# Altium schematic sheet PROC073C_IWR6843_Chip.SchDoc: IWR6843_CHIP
size 431 x 279 mm; Date: Not shown in title block; ApprovedBy: Not shown in title block; CheckedBy: Not shown in title block; Author: Not shown in title block; CompanyName: Not shown in title block; DrawnBy: Charles F. Oladimeji; Engineer: Not shown in title block; Organization: Not shown in title block; Address1: Not shown in title block; Address2: Not shown in title block; Address3: Not shown in title block; Address4: Not shown in title block; DocumentNumber: 4; Revision: Use project parameter SCH_Rev; SheetNumber: 4; SheetTotal: 13; PageSetup: Record=PageOptions¦CenterHorizontal=True¦CenterVertical=True¦PrintScale=1.00¦XCorrection=1.00¦YCorrection=1.00¦PrintKind=0¦BorderSize=5000000¦LeftOffset=0¦BottomOffset=0¦Orientation=2¦PaperLength=1000¦PaperWidth=1000¦Scale=100¦PaperSource=15¦PrintQuality=600¦MediaType=1¦DitherType=10¦PaperKind=Letter¦PrintScaleMode=1
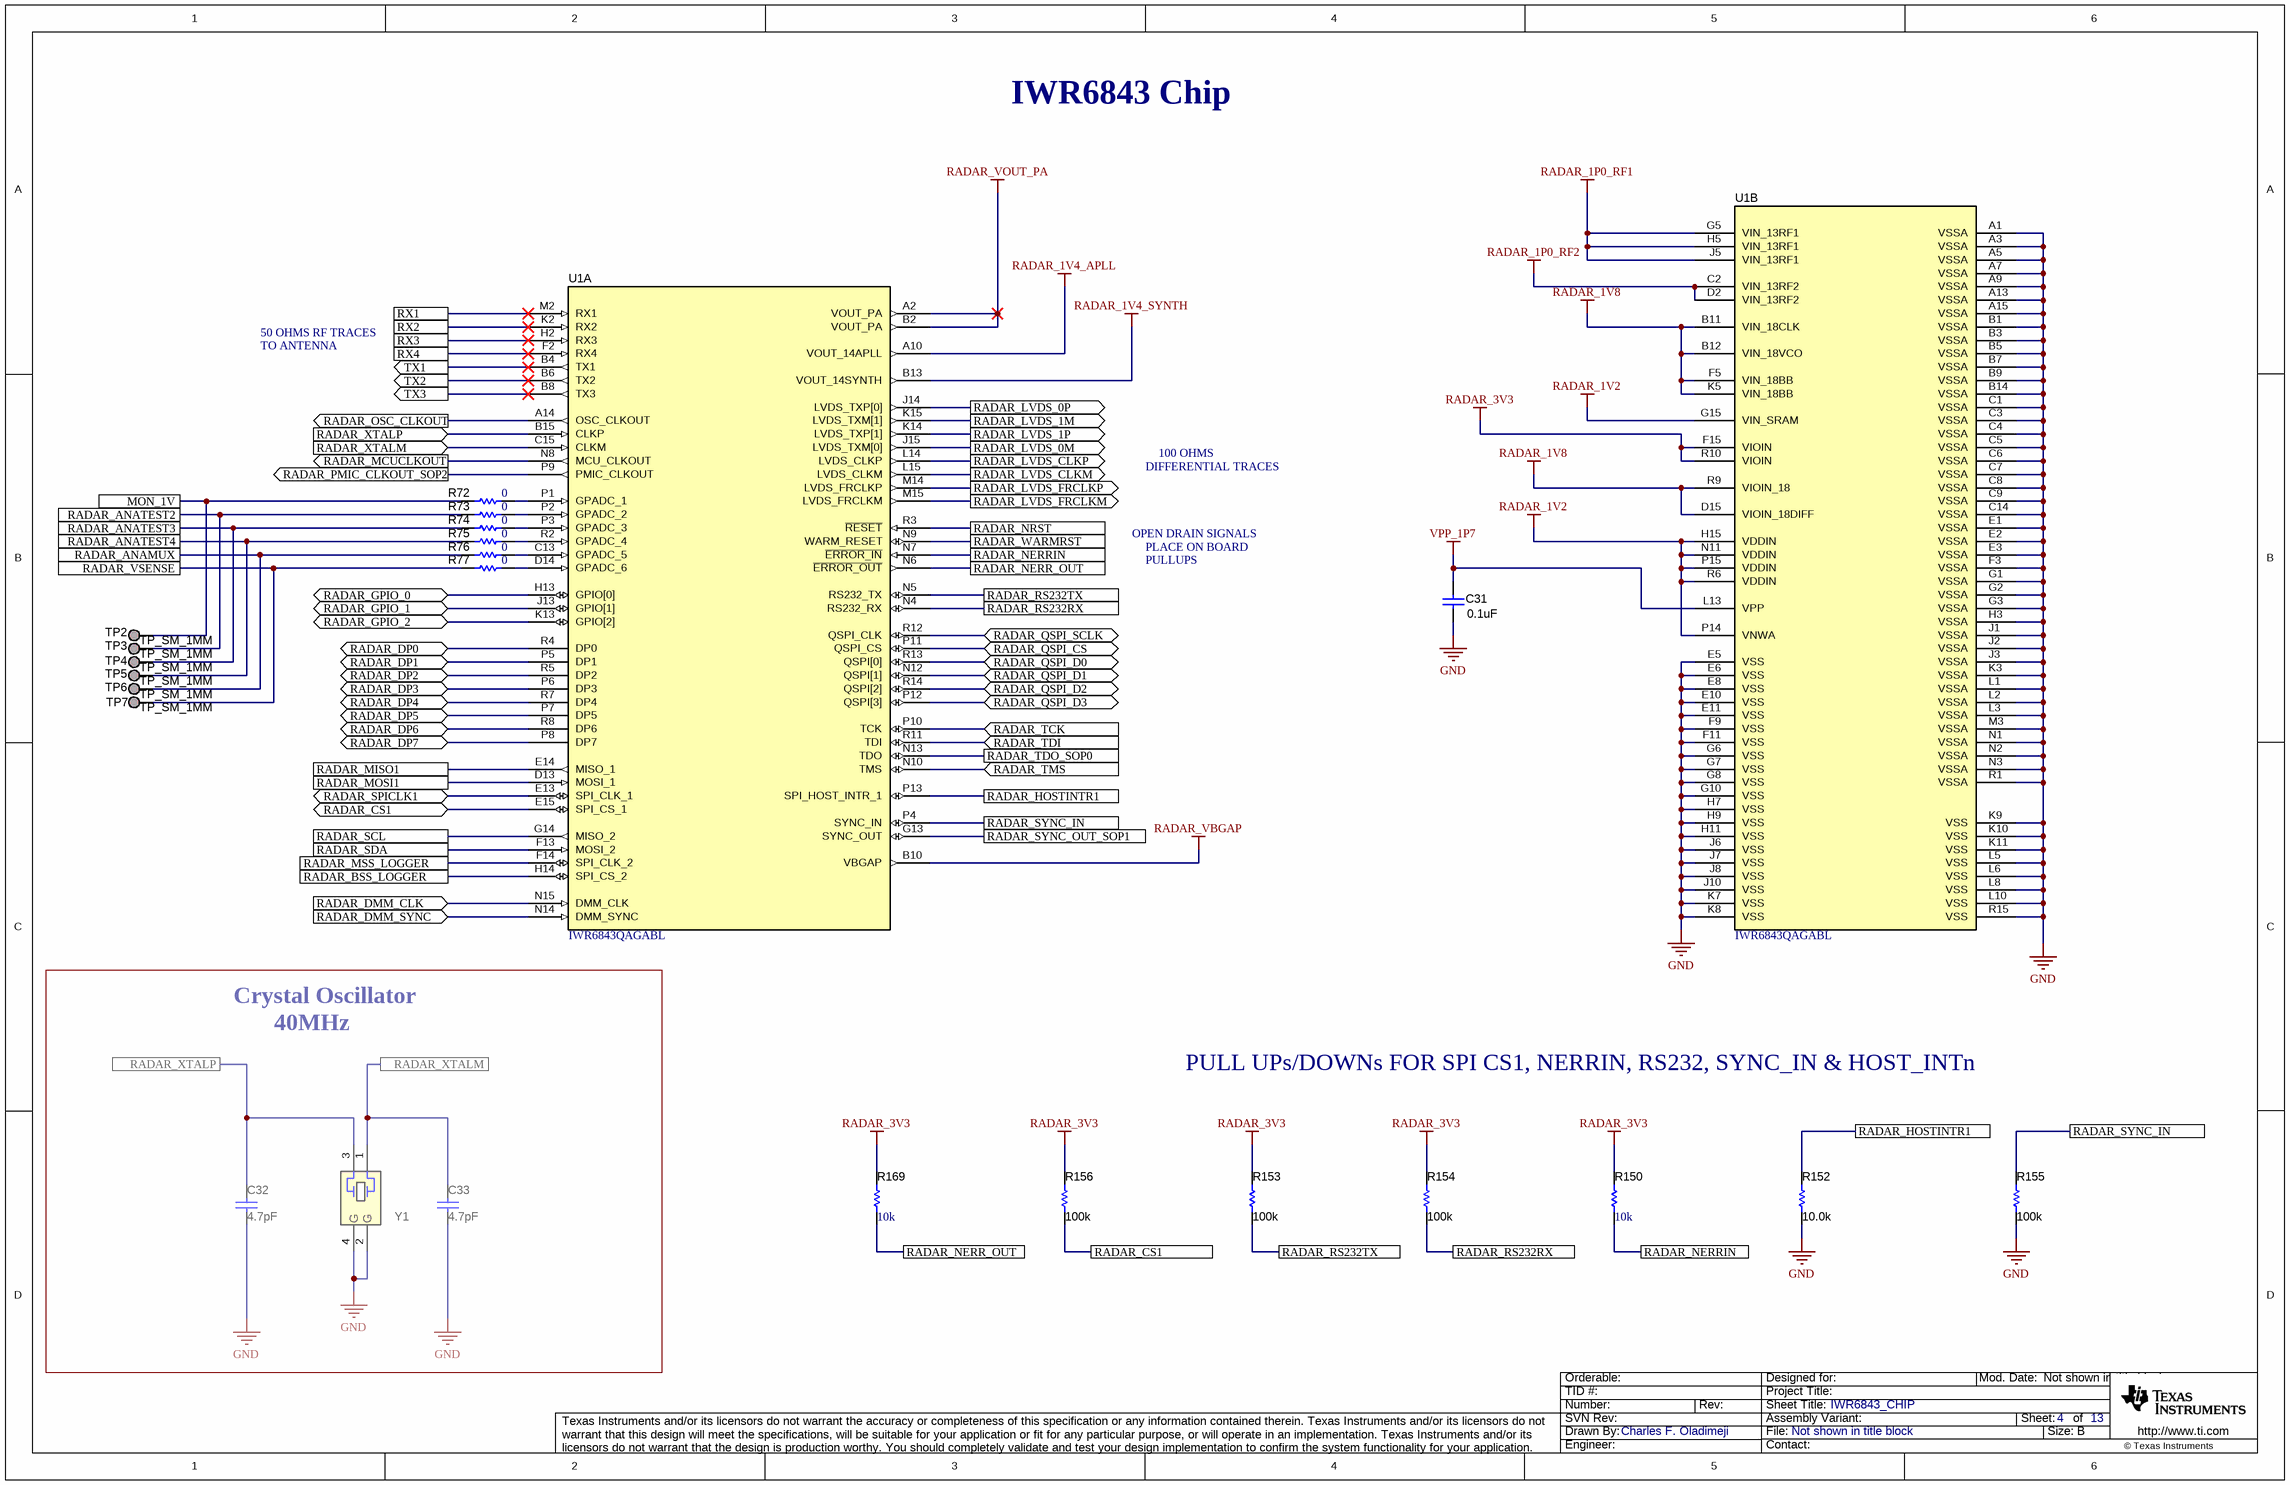
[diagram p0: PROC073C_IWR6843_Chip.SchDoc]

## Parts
C31  ValueDisplayed: 0.1uF  [0201]  (hidden comment: GRM033C71A104KE14D)
C32  ValueDisplayed: 4.7pF  [0402L]  (hidden comment: GJM1555C1H4R7BB01D)
C33  ValueDisplayed: 4.7pF  [0402L]  (hidden comment: GJM1555C1H4R7BB01D)
R72  ValueDisplayed: 0  [0402]  (hidden comment: ERJ-2GE0R00X)
R73  ValueDisplayed: 0  [0402]  (hidden comment: ERJ-2GE0R00X)
R74  ValueDisplayed: 0  [0402]  (hidden comment: ERJ-2GE0R00X)
R75  ValueDisplayed: 0  [0402]  (hidden comment: ERJ-2GE0R00X)
R76  ValueDisplayed: 0  [0402]  (hidden comment: ERJ-2GE0R00X)
R77  ValueDisplayed: 0  [0402]  (hidden comment: ERJ-2GE0R00X)
R150  value 10k  [0402]  (hidden comment: CRCW040210K0JNED)
R152  ValueDisplayed: 10.0k  [0402L]  (hidden comment: CRCW040210K0FKED)
R153  ValueDisplayed: 100k  [0402L]  (hidden comment: CRCW0402100KFKED)
R154  ValueDisplayed: 100k  [0402L]  (hidden comment: CRCW0402100KFKED)
R155  ValueDisplayed: 100k  [0402L]  (hidden comment: CRCW0402100KFKED)
R156  ValueDisplayed: 100k  [0402L]  (hidden comment: CRCW0402100KFKED)
R169  value 10k  [0402]  (hidden comment: CRCW040210K0JNED)
TP2  TP_SM_1MM  [TP_SM_1MM]  (no BOM)
TP3  TP_SM_1MM  [TP_SM_1MM]  (no BOM)
TP4  TP_SM_1MM  [TP_SM_1MM]  (no BOM)
TP5  TP_SM_1MM  [TP_SM_1MM]  (no BOM)
TP6  TP_SM_1MM  [TP_SM_1MM]  (no BOM)
TP7  TP_SM_1MM  [TP_SM_1MM]  (no BOM)
U1  IWR6843QAGABL  [ABL0161B]  (parts A,B of 2)
Y1  CX3225SA40000D0PTWCC  [Kyocera_CX3225SA]  (value not drawn)

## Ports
MON_1V, RADAR_ANAMUX, RADAR_ANATEST2, RADAR_ANATEST3, RADAR_ANATEST4, RADAR_BSS_LOGGER, RADAR_CS1, RADAR_CS1 (bidir), RADAR_DMM_CLK (in), RADAR_DMM_SYNC (in), RADAR_DP0 (bidir), RADAR_DP1 (bidir), RADAR_DP2 (bidir), RADAR_DP3 (bidir), RADAR_DP4 (bidir), RADAR_DP5 (bidir), RADAR_DP6 (bidir), RADAR_DP7 (bidir), RADAR_GPIO_0 (bidir), RADAR_GPIO_1 (bidir), RADAR_GPIO_2 (bidir), RADAR_HOSTINTR1, RADAR_LVDS_0M (out), RADAR_LVDS_0P (out), RADAR_LVDS_1M (out), RADAR_LVDS_1P (out), RADAR_LVDS_CLKM (out), RADAR_LVDS_CLKP (out), RADAR_LVDS_FRCLKM (out), RADAR_LVDS_FRCLKP (out), RADAR_MCUCLKOUT (out), RADAR_MISO1, RADAR_MOSI1, RADAR_MSS_LOGGER, RADAR_NERR_OUT, RADAR_NERRIN, RADAR_NRST, RADAR_OSC_CLKOUT (out), RADAR_PMIC_CLKOUT_SOP2 (out), RADAR_QSPI_CS (bidir), RADAR_QSPI_D0 (bidir), RADAR_QSPI_D1 (bidir), RADAR_QSPI_D2 (bidir), RADAR_QSPI_D3 (bidir), RADAR_QSPI_SCLK (bidir), RADAR_RS232RX, RADAR_RS232TX, RADAR_SCL, RADAR_SDA, RADAR_SPICLK1 (bidir), RADAR_SYNC_IN, RADAR_SYNC_OUT_SOP1, RADAR_TCK (in), RADAR_TDI (in), RADAR_TDO_SOP0, RADAR_TMS (in), RADAR_VSENSE, RADAR_WARMRST, RADAR_XTALM, RADAR_XTALM (in), RADAR_XTALP, RADAR_XTALP (in), RX1, RX2, RX3, RX4, TX1 (out), TX2 (out), TX3 (out)

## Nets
GND: C31.1 C32.1 C33.1 R152.1 R155.1 U1.A1(VSSA) U1.A3(VSSA) U1.A5(VSSA) U1.A7(VSSA) U1.A9(VSSA) U1.A13(VSSA) U1.A15(VSSA) U1.B1(VSSA) U1.B3(VSSA) U1.B5(VSSA) U1.B7(VSSA) U1.B9(VSSA) U1.B14(VSSA) U1.C1(VSSA) U1.C3(VSSA) U1.C4(VSSA) U1.C5(VSSA) U1.C6(VSSA) U1.C7(VSSA) U1.C8(VSSA) U1.C9(VSSA) U1.C14(VSSA) U1.E1(VSSA) U1.E2(VSSA) U1.E3(VSSA) U1.E5(VSS) U1.E6(VSS) U1.E8(VSS) U1.E10(VSS) U1.E11(VSS) U1.F3(VSSA) U1.F9(VSS) U1.F11(VSS) U1.G1(VSSA) U1.G2(VSSA) U1.G3(VSSA) U1.G6(VSS) U1.G7(VSS) U1.G8(VSS) U1.G10(VSS) U1.H3(VSSA) U1.H7(VSS) U1.H9(VSS) U1.H11(VSS) U1.J1(VSSA) U1.J2(VSSA) U1.J3(VSSA) U1.J6(VSS) U1.J7(VSS) U1.J8(VSS) U1.J10(VSS) U1.K3(VSSA) U1.K7(VSS) U1.K8(VSS) U1.K9(VSS) U1.K10(VSS) U1.K11(VSS) U1.L1(VSSA) U1.L2(VSSA) U1.L3(VSSA) U1.L5(VSS) U1.L6(VSS) U1.L8(VSS) U1.L10(VSS) U1.M3(VSSA) U1.N1(VSSA) U1.N2(VSSA) U1.N3(VSSA) U1.R1(VSSA) U1.R15(VSS) Y1.2(GND) Y1.4(GND)
RADAR_1P0_RF1: U1.G5(VIN_13RF1) U1.H5(VIN_13RF1) U1.J5(VIN_13RF1)
RADAR_1P0_RF2: U1.C2(VIN_13RF2) U1.D2(VIN_13RF2)
RADAR_1V2: U1.G15(VIN_SRAM) U1.H15(VDDIN) U1.N11(VDDIN) U1.P14(VNWA) U1.P15(VDDIN) U1.R6(VDDIN)
RADAR_1V4_APLL: U1.A10(VOUT_14APLL)
RADAR_1V4_SYNTH: U1.B13(VOUT_14SYNTH)
RADAR_1V8: U1.B11(VIN_18CLK) U1.B12(VIN_18VCO) U1.D15(VIOIN_18DIFF) U1.F5(VIN_18BB) U1.K5(VIN_18BB) U1.R9(VIOIN_18)
RADAR_3V3: R150.2 R153.2 R154.2 R156.2 R169.2 U1.F15(VIOIN) U1.R10(VIOIN)
RADAR_VBGAP: U1.B10(VBGAP)
RADAR_VOUT_PA: U1.A2(VOUT_PA) U1.B2(VOUT_PA)
VPP_1P7: C31.2 U1.L13(VPP)
MON_1V: R72.1 TP2.1 ; port MON_1V
RADAR_ANAMUX: R76.1 TP6.1 ; port RADAR_ANAMUX
RADAR_ANATEST2: R73.1 TP3.1 ; port RADAR_ANATEST2
RADAR_ANATEST3: R74.1 TP4.1 ; port RADAR_ANATEST3
RADAR_ANATEST4: R75.1 TP5.1 ; port RADAR_ANATEST4
RADAR_BSS_LOGGER: U1.H14(SPI_CS_2) ; port RADAR_BSS_LOGGER
RADAR_CS1: R156.1 U1.E15(SPI_CS_1) ; port RADAR_CS1
RADAR_DMM_CLK: U1.N15(DMM_CLK) ; port RADAR_DMM_CLK
RADAR_DMM_SYNC: U1.N14(DMM_SYNC) ; port RADAR_DMM_SYNC
RADAR_DP0: U1.R4(DP0) ; port RADAR_DP0
RADAR_DP1: U1.P5(DP1) ; port RADAR_DP1
RADAR_DP2: U1.R5(DP2) ; port RADAR_DP2
RADAR_DP3: U1.P6(DP3) ; port RADAR_DP3
RADAR_DP4: U1.R7(DP4) ; port RADAR_DP4
RADAR_DP5: U1.P7(DP5) ; port RADAR_DP5
RADAR_DP6: U1.R8(DP6) ; port RADAR_DP6
RADAR_DP7: U1.P8(DP7) ; port RADAR_DP7
RADAR_GPIO_0: U1.H13(GPIO[0]) ; port RADAR_GPIO_0
RADAR_GPIO_1: U1.J13(GPIO[1]) ; port RADAR_GPIO_1
RADAR_GPIO_2: U1.K13(GPIO[2]) ; port RADAR_GPIO_2
RADAR_HOSTINTR1: R152.2 U1.P13(SPI_HOST_INTR_1) ; port RADAR_HOSTINTR1
RADAR_LVDS_0M: U1.J15(LVDS_TXM[0]) ; port RADAR_LVDS_0M
RADAR_LVDS_0P: U1.J14(LVDS_TXP[0]) ; port RADAR_LVDS_0P
RADAR_LVDS_1M: U1.K15(LVDS_TXM[1]) ; port RADAR_LVDS_1M
RADAR_LVDS_1P: U1.K14(LVDS_TXP[1]) ; port RADAR_LVDS_1P
RADAR_LVDS_CLKM: U1.L15(LVDS_CLKM) ; port RADAR_LVDS_CLKM
RADAR_LVDS_CLKP: U1.L14(LVDS_CLKP) ; port RADAR_LVDS_CLKP
RADAR_LVDS_FRCLKM: U1.M15(LVDS_FRCLKM) ; port RADAR_LVDS_FRCLKM
RADAR_LVDS_FRCLKP: U1.M14(LVDS_FRCLKP) ; port RADAR_LVDS_FRCLKP
RADAR_MCUCLKOUT: U1.N8(MCU_CLKOUT) ; port RADAR_MCUCLKOUT
RADAR_MISO1: U1.E14(MISO_1) ; port RADAR_MISO1
RADAR_MOSI1: U1.D13(MOSI_1) ; port RADAR_MOSI1
RADAR_MSS_LOGGER: U1.F14(SPI_CLK_2) ; port RADAR_MSS_LOGGER
RADAR_NERR_OUT: R169.1 U1.N6(~{ERROR_OUT}) ; port RADAR_NERR_OUT
RADAR_NERRIN: R150.1 U1.N7(~{ERROR_IN}) ; port RADAR_NERRIN
RADAR_NRST: U1.R3(~{RESET}) ; port RADAR_NRST
RADAR_OSC_CLKOUT: U1.A14(OSC_CLKOUT) ; port RADAR_OSC_CLKOUT
RADAR_PMIC_CLKOUT_SOP2: U1.P9(PMIC_CLKOUT) ; port RADAR_PMIC_CLKOUT_SOP2
RADAR_QSPI_CS: U1.P11(QSPI_CS) ; port RADAR_QSPI_CS
RADAR_QSPI_D0: U1.R13(QSPI[0]) ; port RADAR_QSPI_D0
RADAR_QSPI_D1: U1.N12(QSPI[1]) ; port RADAR_QSPI_D1
RADAR_QSPI_D2: U1.R14(QSPI[2]) ; port RADAR_QSPI_D2
RADAR_QSPI_D3: U1.P12(QSPI[3]) ; port RADAR_QSPI_D3
RADAR_QSPI_SCLK: U1.R12(QSPI_CLK) ; port RADAR_QSPI_SCLK
RADAR_RS232RX: R154.1 U1.N4(RS232_RX) ; port RADAR_RS232RX
RADAR_RS232TX: R153.1 U1.N5(RS232_TX) ; port RADAR_RS232TX
RADAR_SCL: U1.G14(MISO_2) ; port RADAR_SCL
RADAR_SDA: U1.F13(MOSI_2) ; port RADAR_SDA
RADAR_SPICLK1: U1.E13(SPI_CLK_1) ; port RADAR_SPICLK1
RADAR_SYNC_IN: R155.2 U1.P4(SYNC_IN) ; port RADAR_SYNC_IN
RADAR_SYNC_OUT_SOP1: U1.G13(SYNC_OUT) ; port RADAR_SYNC_OUT_SOP1
RADAR_TCK: U1.P10(TCK) ; port RADAR_TCK
RADAR_TDI: U1.R11(TDI) ; port RADAR_TDI
RADAR_TDO_SOP0: U1.N13(TDO) ; port RADAR_TDO_SOP0
RADAR_TMS: U1.N10(TMS) ; port RADAR_TMS
RADAR_VSENSE: R77.1 TP7.1 ; port RADAR_VSENSE
RADAR_WARMRST: U1.N9(WARM_RESET) ; port RADAR_WARMRST
RADAR_XTALM: C33.2 U1.C15(CLKM) Y1.1 ; port RADAR_XTALM
RADAR_XTALP: C32.2 U1.B15(CLKP) Y1.3 ; port RADAR_XTALP
RX1: U1.M2(RX1) ; port RX1
RX2: U1.K2(RX2) ; port RX2
RX3: U1.H2(RX3) ; port RX3
RX4: U1.F2(RX4) ; port RX4
TX1: U1.B4(TX1) ; port TX1
TX2: U1.B6(TX2) ; port TX2
TX3: U1.B8(TX3) ; port TX3
NetR72_2: R72.2 U1.P1(GPADC_1)
NetR73_2: R73.2 U1.P2(GPADC_2)
NetR74_2: R74.2 U1.P3(GPADC_3)
NetR75_2: R75.2 U1.R2(GPADC_4)
NetR76_2: R76.2 U1.C13(GPADC_5)
NetR77_2: R77.2 U1.D14(GPADC_6)

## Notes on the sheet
- IWR6843 Chip
- 50 OHMS RF TRACES
- TO ANTENNA
- DIFFERENTIAL TRACES
- 100 OHMS
- OPEN DRAIN SIGNALS
- PLACE ON BOARD
- PULLUPS
- Crystal Oscillator
- 40MHz
- PULL UPs/DOWNs FOR SPI CS1, NERRIN, RS232, SYNC_IN & HOST_INTn

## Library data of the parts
C31 = CMP-0064969-1: CAP, CERM, 0.1 uF, 10 V,+/- 10%, X7S, 0201; Manufacturer: MuRata; TaMin_C: -55°C; Polarized: N; SizeAreaWB_mm2: 2.08; Value1: Unknown; U/M: EA; Value: 0.1uF; TaMax_C: 125°C; SizeZ_mm: 0.26; SizeX_mm: 0.6; SizeY_mm: 0.3; Value2: 10V; SizeArea_mm2: 0.18; Cap_F: 100nF; AEC Category: Q200
C32 C33 = CMP-0006367-2: CAP, CERM, 4.7 pF, 50 V, +/- 2%, C0G/NP0, 0402; Manufacturer: MuRata; TaMin_C: -55°C; Polarized: N; SizeAreaWB_mm2: 3; Value1: Unknown; U/M: EA; Value: 4.7pF; TaMax_C: 125°C; SizeZ_mm: 0.6; SizeX_mm: 1; SizeY_mm: 0.5; Cap_Case: 0402; Value2: 50V; CompType: Capacitor; AEC Category: Q200
R72-R77 = CMP-0026992-3: RES, 0, 5%, 0.1 W, AEC-Q200 Grade 0, 0402; Manufacturer: Panasonic; Power_W: 100mW; TempCo: 600 ppm/C; Value_Code: 0000; Value: 0; EIA_Code: E24; SizeX_mm: 1; SizeY_mm: 0.5; SizeZ_mm: 0.6; Value2: 0.1W; AEC Qualified: Y; VDC_V: 50V; AEC Category: Q200; SizeAreaWB_mm2: 3
R150 R169 = CMP-0026825-5: RES, 10 k, 5%, 0.063 W, AEC-Q200 Grade 0, 0402; Manufacturer: Vishay-Dale; Power_W: 63mW; TempCo: 200 ppm/C; Value_Code: 10k0; EIA_Code: E24; SizeX_mm: 1; SizeY_mm: 0.5; SizeZ_mm: 0.6; Value2: 0.063W; CompType: Resistor; AEC Qualified: Y; VDC_V: 50V; AEC Category: Q200; AEC Grade: 0; INSTALLATION: DNP
R152 = CMP-0025958-3: RES, 10.0 k, 1%, 0.063 W, AEC-Q200 Grade 0, 0402; Manufacturer: Vishay-Dale; Power_W: 63mW; TempCo: 100 ppm/C; Value_Code: 10k0; Value: 10.0k; EIA_Code: E96; Res_ohm: 10k; SizeX_mm: 1; SizeY_mm: 0.5; SizeZ_mm: 0.6; Value2: 0.063W; AEC Qualified: Y; VDC_V: 50V; AEC Category: Q200; AEC Grade: 0
R153-R156 = CMP-0025950-3: RES, 100 k, 1%, 0.063 W, AEC-Q200 Grade 0, 0402; Manufacturer: Vishay-Dale; Power_W: 63mW; TempCo: 100 ppm/C; Value: 100k; EIA_Code: E96; SizeX_mm: 1; SizeY_mm: 0.5; SizeZ_mm: 0.6; Value2: 0.063W; AEC Qualified: Y; VDC_V: 50V; AEC Category: Q200; AEC Grade: 0
TP2-TP7 = CMP-0003825-1: 1mm Test Point, SMT; Manufacturer: Any
U1 = CMP-0081105-1: IWR1843QAGABL, ABL0161B (FCBGA-161); Alternate Manufacturer: Texas Instruments; SizeAreaWB_mm2: 153.76; SizeZ_mm: 1.17; SizeX_mm: 10.4; SizeArea_mm2: 108.16; CompType: IC; AEC Qualified: N; AEC Category: Q200
Y1 = CMP-0004694-3: Crystal, 40 MHz, 8pF, SMD; Manufacturer: Kyocera; TaMin_C: -40°C; Frequency Stability: +/-200ppm; SizeAreaWB_mm2: 14.7; Frequency_Fixed: 40MHz; TaMax_C: 125°C; SizeZ_mm: 0.8; SizeX_mm: 2.5; SizeY_mm: 3.2; SizeArea_mm2: 8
